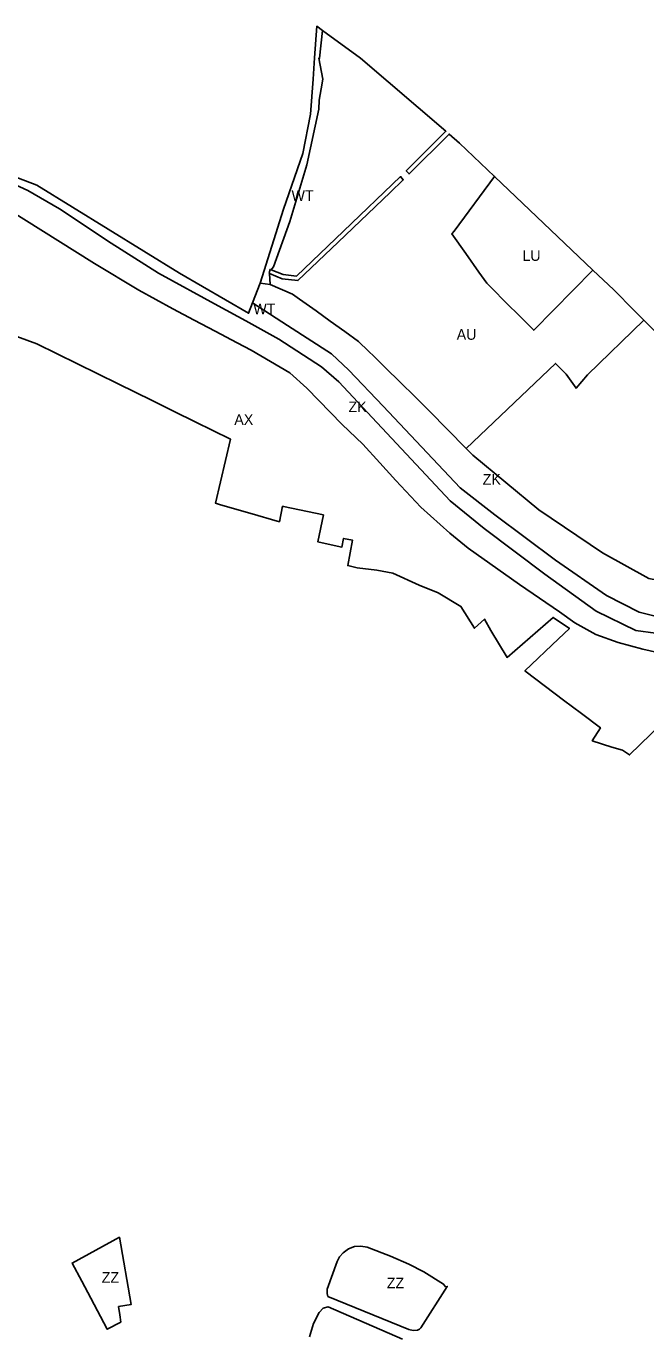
# Model space of a CAD drawing. Extents: x -545779 to -541342, y -1153413 to -1149956.
# Drawn here: x -544124 to -543834, y -1151467 to -1150852 of the extents above; entities that cross this region are included whole.
import ezdxf

# ---------------------------------------------------------------- set-up
doc = ezdxf.new("R2010")
doc.units = 0
for name, color, linetype in [('90640013', 7, 'Continuous'), ('90670013', 7, 'Continuous'), ('90710013', 7, 'Continuous'), ('90750013', 7, 'Continuous'), ('90760013', 7, 'Continuous'), ('90770013', 7, 'Continuous'), ('90910012', 7, 'Continuous')]:
    doc.layers.add(name, color=color, linetype=linetype)

msp = doc.modelspace()

# ---------------------------------------------------------------- linework, layer by layer
at = {"layer": '90640013'}
msp.add_lwpolyline([(-543990.85, -1150893.43), (-543989.72, -1150877.02), (-543989.04, -1150867.04), (-543989.04, -1150867.04), (-543988.016, -1150852.128), (-543985.332, -1150854.093), (-543986.65, -1150867.16), (-543987.01, -1150867.14), (-543985.16, -1150876.98), (-543985.95, -1150881.47), (-543986.89, -1150886.87), (-543987.06, -1150891.11), (-543992.6, -1150917.29), (-544000.69, -1150943.79), (-544008.29, -1150965.17), (-544009.35, -1150966.49), (-544009.85, -1150966.29), (-544010.26, -1150967.9), (-544010.23, -1150968.29), (-544009.79, -1150973.38), (-544014.52, -1150972.79), (-544003.52, -1150937.98), (-543994.59, -1150911.93)], close=True, dxfattribs=at)
for points in [[(-544161.7, -1150910.69), (-544119.43, -1150926.78), (-544052.4, -1150968.07), (-544019.95, -1150986.86), (-544018.08, -1150982.01), (-544001.77, -1150992.57), (-543981.11, -1151005.93), (-543972.98, -1151013.62), (-543956.84, -1151030.46), (-543920.73, -1151068.9), (-543904.45, -1151081.5), (-543875.92, -1151102.77), (-543852.01, -1151119.39), (-543836.64, -1151127.19), (-543820.44, -1151131.33)], [(-543819.74, -1151138.33), (-543838.2, -1151135.78), (-543856.8, -1151126.79), (-543880.87, -1151109.45), (-543909.38, -1151087.89), (-543925.34, -1151074.97), (-543962.01, -1151035.9), (-543977.59, -1151019.13), (-543985.82, -1151012.03), (-544005.73, -1150999.07), (-544021.34, -1150990.47), (-544034.19, -1150983.38), (-544062.24, -1150968.12), (-544084.54, -1150954.05), (-544108.79, -1150937.82), (-544123.65, -1150929.34), (-544147.92, -1150918.16)]]:
    msp.add_lwpolyline(points, dxfattribs=at)
at = {"layer": '90670013'}
for points in [[(-544094.05, -1151449.25), (-544094.05, -1151449.25), (-544098.22, -1151441.35), (-544102.81, -1151432.82), (-544080.63, -1151420.73), (-544075.02, -1151452.28), (-544080.99, -1151453.26), (-544080.41, -1151457.13), (-544079.903, -1151460.528), (-544086.3, -1151463.91)], [(-543944.8, -1151463.97), (-543982.78, -1151448.51), (-543983.05, -1151447.16), (-543983.11, -1151445.08), (-543978.45, -1151432.12), (-543977.23, -1151429.86), (-543975.52, -1151427.97), (-543973.04, -1151426.23), (-543970.28, -1151425.13), (-543967.37, -1151424.91), (-543964.36, -1151425.33), (-543953.41, -1151429.63), (-543944.83, -1151433.37), (-543937.67, -1151436.98), (-543928.47, -1151442.75), (-543927.51, -1151443.98), (-543926.7, -1151443.82), (-543939.06, -1151463.27), (-543939.69, -1151463.92), (-543940.7, -1151464.35), (-543942.7, -1151464.52)]]:
    msp.add_lwpolyline(points, close=True, dxfattribs=at)
msp.add_lwpolyline([(-543991.36, -1151467.47), (-543989.48, -1151461.15), (-543986.86, -1151456.12), (-543984.94, -1151454.08), (-543982.6, -1151453.35), (-543947.72, -1151468.6)], dxfattribs=at)
at = {"layer": '90710013'}
for points in [[(-544147.92, -1150918.16), (-544123.65, -1150929.34), (-544108.79, -1150937.82), (-544084.54, -1150954.05), (-544062.24, -1150968.12), (-544034.19, -1150983.38), (-544021.34, -1150990.47), (-544005.73, -1150999.07), (-543985.82, -1151012.03), (-543977.59, -1151019.13), (-543962.01, -1151035.9), (-543925.34, -1151074.97), (-543909.38, -1151087.89), (-543880.87, -1151109.45), (-543856.8, -1151126.79), (-543838.2, -1151135.78), (-543819.74, -1151138.33)], [(-543810.81, -1151150.09), (-543834.9, -1151144.58), (-543846.48, -1151141.45), (-543857.02, -1151137.69), (-543866.9, -1151132.27), (-543874.03, -1151127.14), (-543892.84, -1151114.23), (-543916.93, -1151097.25), (-543925.58, -1151090.16), (-543939.11, -1151077.93), (-543950.83, -1151065.42), (-543958.4, -1151057.14), (-543966.43, -1151048.43), (-543976.11, -1151039.14), (-543992.63, -1151022.11), (-544000.66, -1151014.88), (-544018.79, -1151004.23), (-544025.31, -1151000.75), (-544035.7, -1150995.23), (-544045.54, -1150990.22), (-544055.56, -1150984.77), (-544071.41, -1150976.11), (-544092.35, -1150963.53), (-544133.39, -1150937.74)], [(-543820.44, -1151131.33), (-543836.64, -1151127.19), (-543852.01, -1151119.39), (-543875.92, -1151102.77), (-543904.45, -1151081.5), (-543920.73, -1151068.9), (-543956.84, -1151030.46), (-543972.98, -1151013.62), (-543981.11, -1151005.93), (-544001.77, -1150992.57), (-544018.08, -1150982.01), (-544014.52, -1150972.79), (-544009.79, -1150973.38), (-543999.31, -1150977.86), (-543996.04, -1150980.21), (-543988.28, -1150985.79), (-543981.64, -1150990.56), (-543974.85, -1150995.44), (-543968.38, -1151000.09), (-543963.71, -1151004.65), (-543961.11, -1151007.19), (-543955.68, -1151012.5), (-543948.83, -1151019.18), (-543941.84, -1151026.08), (-543935.26, -1151032.76), (-543917.81, -1151050.47), (-543914.79, -1151053.54), (-543883.76, -1151079.27), (-543853.83, -1151099.45), (-543832.05, -1151111.38)]]:
    msp.add_lwpolyline(points, dxfattribs=at)
at = {"layer": '90750013'}
msp.add_lwpolyline([(-543985.332, -1150854.093), (-543967.455, -1150867.181), (-543927.383, -1150901.455), (-543946.01, -1150919.98), (-543944.64, -1150921.44), (-543925.852, -1150902.765), (-543920.938, -1150906.967), (-543904.485, -1150922.664), (-543923.54, -1150948.33), (-543924.53, -1150949.66), (-543917.99, -1150958.92), (-543911.9, -1150967.55), (-543908.2, -1150972.79), (-543905.56, -1150975.43), (-543899.32, -1150981.67), (-543892.41, -1150988.59), (-543886.12, -1150994.88), (-543858.414, -1150966.619), (-543848.631, -1150975.952), (-543838.971, -1150985.615), (-543834.398, -1150990.189), (-543860.9, -1151015.8), (-543866.247, -1151022.12), (-543870.92, -1151015.46), (-543875.99, -1151010.48), (-543917.81, -1151050.47), (-543935.26, -1151032.76), (-543941.84, -1151026.08), (-543948.83, -1151019.18), (-543955.68, -1151012.5), (-543961.11, -1151007.19), (-543963.71, -1151004.65), (-543968.38, -1151000.09), (-543974.85, -1150995.44), (-543981.64, -1150990.56), (-543988.28, -1150985.79), (-543996.04, -1150980.21), (-543999.31, -1150977.86), (-544009.79, -1150973.38), (-544010.23, -1150968.29), (-544004.18, -1150970.7), (-543996.79, -1150971.58), (-543977.89, -1150953.5), (-543953.47, -1150930.15), (-543947.35, -1150924.29), (-543948.6, -1150922.72), (-543975.44, -1150948.39), (-543997.5, -1150969.49), (-544003.69, -1150968.75), (-544009.35, -1150966.49), (-544008.29, -1150965.17), (-544000.69, -1150943.79), (-543992.6, -1150917.29), (-543987.06, -1150891.11), (-543986.89, -1150886.87), (-543985.95, -1150881.47), (-543985.16, -1150876.98), (-543987.01, -1150867.14), (-543986.65, -1150867.16)], close=True, dxfattribs=at)
at = {"layer": '90760013'}
for points in [[(-544133.39, -1150937.74), (-544092.35, -1150963.53), (-544071.41, -1150976.11), (-544055.56, -1150984.77), (-544045.54, -1150990.22), (-544035.7, -1150995.23), (-544025.31, -1151000.75), (-544018.79, -1151004.23), (-544000.66, -1151014.88), (-543992.63, -1151022.11), (-543976.11, -1151039.14), (-543966.43, -1151048.43), (-543958.4, -1151057.14), (-543950.83, -1151065.42), (-543939.11, -1151077.93), (-543925.58, -1151090.16), (-543916.93, -1151097.25), (-543892.84, -1151114.23), (-543874.052, -1151127.125), (-543874.03, -1151127.14), (-543866.9, -1151132.27), (-543857.02, -1151137.69), (-543846.48, -1151141.45), (-543834.9, -1151144.58), (-543810.81, -1151150.09)], [(-543821.4, -1151174.93), (-543841.19, -1151194.27), (-543844.56, -1151192), (-543849.54, -1151190.68), (-543858.68, -1151187.64), (-543854.866, -1151181.512), (-543863.714, -1151174.834), (-543872.124, -1151168.485), (-543880.547, -1151162.128), (-543890.282, -1151154.779), (-543874.538, -1151139.776), (-543869.4, -1151134.88), (-543877.03, -1151129.71), (-543898.64, -1151148.47), (-543906.23, -1151135.81), (-543909.27, -1151130.5), (-543913.95, -1151134.8), (-543920.31, -1151124.57), (-543930.93, -1151118.19), (-543939.98, -1151114.51), (-543952.27, -1151108.88), (-543959.81, -1151107.53), (-543969, -1151106.44), (-543973.4, -1151105.4), (-543971.13, -1151093.45), (-543975.37, -1151092.64), (-543976.17, -1151096.66), (-543982.64, -1151095.3), (-543987.45, -1151094.29), (-543984.82, -1151081.57), (-544003.66, -1151077.63), (-544004.04, -1151077.55), (-544005.53, -1151084.79), (-544019.44, -1151080.75), (-544033.15, -1151076.77), (-544035.43, -1151076.11), (-544028.458, -1151046.082), (-544045.079, -1151037.875), (-544054.916, -1151033.017), (-544065.217, -1151027.931), (-544081.204, -1151020.037), (-544119.396, -1151001.178), (-544145.906, -1150991.608)]]:
    msp.add_lwpolyline(points, dxfattribs=at)
msp.add_lwpolyline([(-543712.747, -1151147.495), (-543729.27, -1151141.61), (-543766.25, -1151127.49), (-543803.43, -1151116.87), (-543832.05, -1151111.38), (-543853.83, -1151099.45), (-543883.76, -1151079.27), (-543914.79, -1151053.54), (-543917.81, -1151050.47), (-543875.99, -1151010.48), (-543870.92, -1151015.46), (-543866.247, -1151022.12), (-543860.9, -1151015.8), (-543834.398, -1150990.189), (-543815.282, -1151009.31), (-543779.683, -1151049.534), (-543749.382, -1151091.238)], close=True, dxfattribs=at)
at = {"layer": '90770013'}
msp.add_lwpolyline([(-543858.414, -1150966.619), (-543886.12, -1150994.88), (-543892.41, -1150988.59), (-543899.32, -1150981.67), (-543905.56, -1150975.43), (-543908.2, -1150972.79), (-543911.9, -1150967.55), (-543917.99, -1150958.92), (-543924.53, -1150949.66), (-543923.54, -1150948.33), (-543904.485, -1150922.664)], close=True, dxfattribs=at)
at = {"layer": '90910012'}
msp.add_lwpolyline([(-543917.81, -1151050.47), (-543875.99, -1151010.48), (-543870.92, -1151015.46), (-543866.247, -1151022.12), (-543860.9, -1151015.8), (-543834.398, -1150990.189)], dxfattribs=at)

# ---------------------------------------------------------------- texts
at = {"layer": '90640013'}
for rotation, p in [(360, (-543999.84, -1150934.125)), (0, (-544017.76, -1150987.33))]:
    msp.add_text('WT', height=5, rotation=rotation, dxfattribs=at).set_placement(p)
at = {"layer": '90670013'}
for rotation, p in [(360, (-544088.915, -1151442.105)), (0, (-543955.124, -1151444.715))]:
    msp.add_text('ZZ', height=5, rotation=rotation, dxfattribs=at).set_placement(p)
at = {"layer": '90710013'}
for rotation, p in [(360, (-543973.068, -1151033.334)), (0, (-543910.123, -1151067.385))]:
    msp.add_text('ZK', height=5, rotation=rotation, dxfattribs=at).set_placement(p)
at = {"layer": '90750013'}
msp.add_text('AU', height=5, rotation=0, dxfattribs=at).set_placement((-543922.314, -1150999.348))
at = {"layer": '90760013'}
msp.add_text('AX', height=5, rotation=0, dxfattribs=at).set_placement((-544026.69, -1151039.331))
at = {"layer": '90770013'}
msp.add_text('LU', height=5, rotation=360, dxfattribs=at).set_placement((-543891.472, -1150962.304))

doc.saveas('drawing.dxf')
